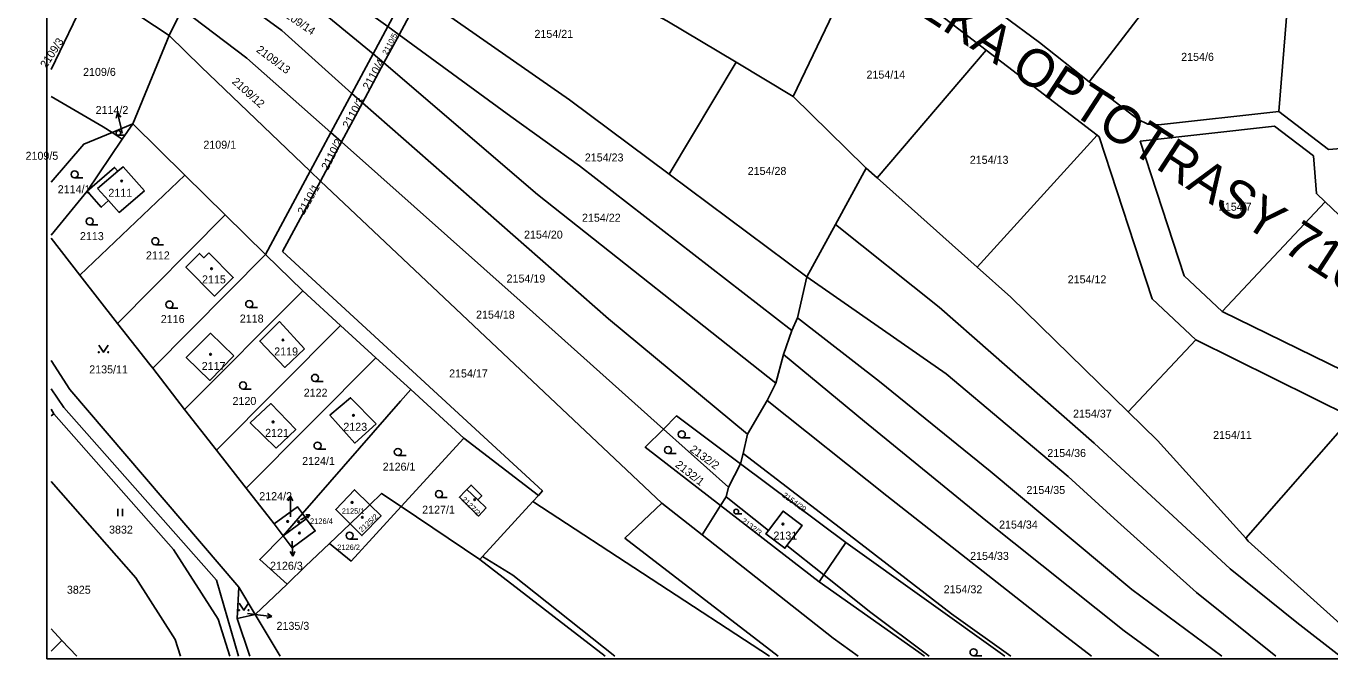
# Model space of a CAD drawing. Extents: x -606208 to -605570, y -1157873 to -1157573.
# Drawn here: x -606207.7 to -605930.7, y -1157873.5 to -1157739 of the extents above; entities that cross this region are included whole.
import ezdxf

# ---------------------------------------------------------------- set-up
doc = ezdxf.new("R2010")
doc.units = 0
for name, color, linetype in [('Vrstva 1', 7, 'Continuous'), ('Vrstva 30', 7, 'Continuous'), ('Vrstva 62', 7, 'Continuous')]:
    doc.layers.add(name, color=color, linetype=linetype)

msp = doc.modelspace()

# ---------------------------------------------------------------- linework, layer by layer
at = {"layer": 'Vrstva 1'}
msp.add_lwpolyline([(-606203.28, -1157873.46), (-605573.29, -1157873.46), (-605573.29, -1157576.47), (-606203.28, -1157576.47)], close=True, dxfattribs=at)
at = {"layer": 'Vrstva 62'}
for p, q in [((-606130.89, -1157739.11), (-606159.85, -1157718.17)), ((-605981.87, -1157750.81), (-605961.6, -1157724.39)), ((-606202.41, -1157748.21), (-606193.72, -1157730.15)), ((-606177.29, -1157741.01), (-606193.72, -1157730.15)), ((-606130.89, -1157739.11), (-606126.5, -1157730.93)), ((-606128.47, -1157740.84), (-606123.99, -1157732.49)), ((-606003.76, -1157744.1), (-606016.54, -1157734.29)), ((-605939.73, -1157734.56), (-605941.6, -1157757.14)), ((-606177.29, -1157741.01), (-606174.52, -1157735.38)), ((-606133.98, -1157744.86), (-606130.89, -1157739.11)), ((-606128.47, -1157740.84), (-606130.89, -1157739.11)), ((-606177.29, -1157741.01), (-606185.06, -1157759.77)), ((-606131.67, -1157746.79), (-606128.47, -1157740.84)), ((-606138.5, -1157753.29), (-606133.98, -1157744.86)), ((-606131.67, -1157746.79), (-606133.98, -1157744.86)), ((-606003.76, -1157744.1), (-606026.9, -1157771.24)), ((-605980.17, -1157762.2), (-606003.76, -1157744.1)), ((-606136.24, -1157755.3), (-606131.67, -1157746.79)), ((-606071.11, -1157770.44), (-606056.89, -1157746.69)), ((-606056.89, -1157746.69), (-606044.76, -1157753.96)), ((-606142.97, -1157761.61), (-606138.5, -1157753.29)), ((-606136.24, -1157755.3), (-606138.5, -1157753.29)), ((-606140.69, -1157763.6), (-606136.24, -1157755.3)), ((-606189.45, -1157761.59), (-606185.06, -1157759.77)), ((-606188.29, -1157757.46), (-606188.55, -1157758.54)), ((-606187.61, -1157760.38), (-606188.29, -1157757.46)), ((-606188.29, -1157757.46), (-606187.57, -1157758.32)), ((-606185.06, -1157759.77), (-606187.26, -1157763.02)), ((-606173.97, -1157770.68), (-606185.06, -1157759.77)), ((-606187.26, -1157763.02), (-606189.45, -1157761.59)), ((-606188.08, -1157762.2), (-606186.9, -1157762.2)), ((-606187.3, -1157761.72), (-606187.61, -1157760.38)), ((-606147.38, -1157769.84), (-606142.97, -1157761.61)), ((-606140.69, -1157763.6), (-606142.97, -1157761.61)), ((-605980.17, -1157762.2), (-606005.69, -1157790.23)), ((-606145.18, -1157771.95), (-606140.69, -1157763.6)), ((-606173.97, -1157770.68), (-606196.3, -1157791.9)), ((-606192.5, -1157773.52), (-606188.21, -1157769.85)), ((-606165.41, -1157779.09), (-606173.97, -1157770.68)), ((-606156.86, -1157787.5), (-606147.38, -1157769.84)), ((-606145.18, -1157771.95), (-606147.38, -1157769.84)), ((-606041.87, -1157792.26), (-606071.11, -1157770.44)), ((-606035.78, -1157781.12), (-606029.24, -1157769.15)), ((-606029.24, -1157769.15), (-606026.9, -1157771.24)), ((-606197.4, -1157771.25), (-606195.65, -1157771.25)), ((-606192.5, -1157773.52), (-606190.23, -1157776.04)), ((-606153.2, -1157786.89), (-606145.18, -1157771.95)), ((-606072.68, -1157840.36), (-606145.18, -1157771.95)), ((-606026.9, -1157771.24), (-606005.69, -1157790.23)), ((-605953.58, -1157799.65), (-605931.72, -1157776.35)), ((-606188.29, -1157802.2), (-606165.41, -1157779.09)), ((-606156.86, -1157787.5), (-606165.41, -1157779.09)), ((-606194.2, -1157781.23), (-606192.45, -1157781.23)), ((-606041.87, -1157792.26), (-606035.78, -1157781.12)), ((-606202.41, -1157784.06), (-606196.3, -1157791.9)), ((-606180.8, -1157811.7), (-606156.86, -1157787.5)), ((-606180.24, -1157785.45), (-606178.49, -1157785.45)), ((-606148.94, -1157795.28), (-606156.86, -1157787.5)), ((-606196.3, -1157791.9), (-606188.29, -1157802.2)), ((-606043.85, -1157800.98), (-606041.87, -1157792.26)), ((-606174.05, -1157820.44), (-606148.94, -1157795.28)), ((-606140.91, -1157802.61), (-606148.94, -1157795.28)), ((-606177.25, -1157798.91), (-606175.5, -1157798.91)), ((-606160.3, -1157798.81), (-606158.55, -1157798.81)), ((-606045.05, -1157803.71), (-606043.85, -1157800.98)), ((-606167.27, -1157829.08), (-606140.91, -1157802.61)), ((-606133.39, -1157809.47), (-606140.91, -1157802.61)), ((-606046.81, -1157808.74), (-606045.05, -1157803.71)), ((-605959.22, -1157805.66), (-605973.57, -1157820.96)), ((-605926.07, -1157822.08), (-605959.22, -1157805.66)), ((-606160.96, -1157837.17), (-606133.39, -1157809.47)), ((-606126, -1157816.22), (-606133.39, -1157809.47)), ((-606048.4, -1157814.88), (-606046.81, -1157808.74)), ((-606180.8, -1157811.7), (-606174.05, -1157820.44)), ((-606146.34, -1157814.5), (-606144.59, -1157814.5)), ((-606050.27, -1157818.52), (-606048.4, -1157814.88)), ((-606202.41, -1157816.09), (-606199.69, -1157820.04)), ((-606161.63, -1157816.11), (-606159.88, -1157816.11)), ((-606114.7, -1157826.53), (-606126, -1157816.22)), ((-606201.78, -1157821.35), (-606202.41, -1157820.41)), ((-606199.69, -1157820.04), (-606167.24, -1157856.73)), ((-606174.05, -1157820.44), (-606167.27, -1157829.08)), ((-606054.42, -1157825.73), (-606050.27, -1157818.52)), ((-606201.78, -1157821.35), (-606202.41, -1157821.83)), ((-605926.07, -1157822.08), (-605948.61, -1157847.83)), ((-606058.49, -1157836.99), (-606072.32, -1157824.61)), ((-606055.38, -1157829.79), (-606054.42, -1157825.73)), ((-606145.79, -1157828.9), (-606144.04, -1157828.9)), ((-606128.03, -1157841.09), (-606114.7, -1157826.53)), ((-606098.87, -1157838.71), (-606114.7, -1157826.53)), ((-606068.41, -1157826.49), (-606066.66, -1157826.49)), ((-606167.27, -1157829.08), (-606160.96, -1157837.17)), ((-606128.73, -1157830.23), (-606126.98, -1157830.23)), ((-606071.33, -1157829.83), (-606069.58, -1157829.83)), ((-606055.91, -1157832.02), (-606055.38, -1157829.79)), ((-606058.49, -1157836.99), (-606055.91, -1157832.02)), ((-606160.96, -1157837.17), (-606154.97, -1157844.72)), ((-606058.97, -1157839.03), (-606058.49, -1157836.99)), ((-606151.56, -1157838.88), (-606152.06, -1157839.88)), ((-606151.56, -1157841.88), (-606151.56, -1157838.88)), ((-606151.56, -1157838.88), (-606151.06, -1157839.88)), ((-606120, -1157839.19), (-606118.25, -1157839.19)), ((-606114.05, -1157837.45), (-606111.74, -1157839.67)), ((-606110.73, -1157851.67), (-606100.03, -1157839.98)), ((-606100.03, -1157839.98), (-606098.87, -1157838.71)), ((-606049.75, -1157872.87), (-606100.03, -1157839.98)), ((-606060.18, -1157840.86), (-606058.97, -1157839.03)), ((-606050.01, -1157846.2), (-606058.97, -1157839.03)), ((-606188.19, -1157843.1), (-606188.19, -1157841.6)), ((-606187.19, -1157843.1), (-606187.19, -1157841.6)), ((-606153.08, -1157847.3), (-606148.97, -1157842.59)), ((-606151.56, -1157843.25), (-606151.56, -1157841.88)), ((-606149.4, -1157843.92), (-606147.41, -1157842.81)), ((-606148.97, -1157842.59), (-606148.17, -1157843.68)), ((-606147.41, -1157842.81), (-606148.26, -1157842.85)), ((-606147.41, -1157842.81), (-606147.89, -1157843.52)), ((-606138.89, -1157844.74), (-606134.7, -1157840.73)), ((-606128.03, -1157841.09), (-606111.34, -1157852.33)), ((-606072.68, -1157840.36), (-606064.09, -1157847.08)), ((-606064.09, -1157847.08), (-606060.18, -1157840.86)), ((-606056.83, -1157842.65), (-606055.66, -1157842.65)), ((-606154.97, -1157844.72), (-606153.08, -1157847.3)), ((-606148.17, -1157843.68), (-606153.08, -1157847.3)), ((-606143.27, -1157848.94), (-606138.89, -1157844.74)), ((-606151.17, -1157848.41), (-606151.16, -1157848.62)), ((-606138.98, -1157848.01), (-606137.23, -1157848.01)), ((-606151.06, -1157851.62), (-606151.59, -1157850.64)), ((-606151.16, -1157848.62), (-606151.06, -1157851.62)), ((-606151.06, -1157851.62), (-606150.59, -1157850.6)), ((-606038.21, -1157855.62), (-606033.59, -1157848.72)), ((-606111.34, -1157852.33), (-606110.73, -1157851.67)), ((-606167.24, -1157856.73), (-606162.59, -1157872.87)), ((-606039.19, -1157857.08), (-606038.21, -1157855.62)), ((-606162.53, -1157858.2), (-606162.86, -1157864.9)), ((-606159.01, -1157864.02), (-606162.53, -1157858.2)), ((-606152.26, -1157857.55), (-606159.01, -1157864.02)), ((-606159.01, -1157864.02), (-606162.86, -1157864.9)), ((-606160.67, -1157863.8), (-606158.48, -1157864.08)), ((-606158.48, -1157864.08), (-606155.5, -1157864.45)), ((-606155.5, -1157864.45), (-606156.56, -1157864.82)), ((-606155.5, -1157864.45), (-606156.43, -1157863.83)), ((-606200.08, -1157869.51), (-606202.41, -1157867.04)), ((-606202.41, -1157871.81), (-606200.08, -1157869.51)), ((-606196.91, -1157872.87), (-606200.08, -1157869.51)), ((-606006.42, -1157872.8), (-606004.67, -1157872.8))]:
    msp.add_line(p, q, dxfattribs=at)
for points in [[(-605985.7, -1157707.69), (-606001.7, -1157728.24), (-606000.3, -1157736.67), (-605992.45, -1157742.47), (-605981.87, -1157750.81)], [(-606056.89, -1157746.69), (-606071.62, -1157737.87), (-606088.96, -1157728.54), (-606113.74, -1157715.77)], [(-606133.98, -1157744.86), (-606143.4, -1157737.14), (-606163.89, -1157722.28)], [(-606138.5, -1157753.29), (-606153.37, -1157739.93), (-606169.28, -1157728.25)], [(-606031.93, -1157728.32), (-606035.41, -1157734.5), (-606044.76, -1157753.96)], [(-606123.99, -1157732.49), (-606092.27, -1157754.64), (-606071.11, -1157770.44)], [(-606142.97, -1157761.61), (-606160.8, -1157745.8), (-606174.52, -1157735.38)], [(-606147.38, -1157769.84), (-606170.48, -1157747.64), (-606177.29, -1157741.01)], [(-606045.05, -1157803.71), (-606090.11, -1157768.67), (-606104.75, -1157758.18), (-606128.47, -1157740.84)], [(-606048.4, -1157814.88), (-606099.09, -1157774.75), (-606131.67, -1157746.79)], [(-605981.87, -1157750.81), (-605971.44, -1157758.81), (-605969.4, -1157759.83), (-605967.12, -1157760.01), (-605941.6, -1157757.14)], [(-606189.45, -1157761.59), (-606191.32, -1157760.37), (-606202.41, -1157753.93)], [(-606044.76, -1157753.96), (-606029.55, -1157768.87), (-606029.24, -1157769.15)], [(-606054.42, -1157825.73), (-606083.97, -1157801.22), (-606136.24, -1157755.3)], [(-605941.6, -1157757.14), (-605931.04, -1157765.25), (-605923.02, -1157764.61), (-605918.26, -1157759.56)], [(-606202.41, -1157772.15), (-606195.45, -1157764.08), (-606189.45, -1157761.59)], [(-605959.22, -1157805.66), (-605968.49, -1157796.97), (-605979.72, -1157762.54), (-605980.17, -1157762.2)], [(-605931.72, -1157776.35), (-605933.58, -1157774.6), (-605934.23, -1157766.58), (-605942.47, -1157760.26), (-605971, -1157763.47), (-605961.68, -1157792.05), (-605953.58, -1157799.65)], [(-606187.26, -1157763.02), (-606194.76, -1157774.09), (-606202.41, -1157783.43)], [(-606072.32, -1157824.61), (-606102.77, -1157797.36), (-606140.69, -1157763.6)], [(-606182.56, -1157774), (-606187.09, -1157768.89), (-606188.21, -1157769.85), (-606188.91, -1157769.03), (-606194.76, -1157774.09), (-606191.72, -1157777.5), (-606190.23, -1157776.04), (-606187.95, -1157778.58), (-606182.56, -1157774)], [(-605953.58, -1157799.65), (-605927.83, -1157812.28), (-605920.8, -1157811.02), (-605907.64, -1157797.07), (-605907.89, -1157788.58), (-605918.83, -1157778.27), (-605928.82, -1157779.07), (-605931.72, -1157776.35)], [(-605928.51, -1157872.87), (-605937.76, -1157865.73), (-605951.92, -1157854.34), (-605980.77, -1157827.6), (-606013.72, -1157798.74), (-606035.78, -1157781.12)], [(-606168.87, -1157787.17), (-606169.93, -1157788.21), (-606170.83, -1157787.29), (-606173.76, -1157790.23), (-606167.66, -1157796.36), (-606163.68, -1157792.38), (-606168.87, -1157787.17)], [(-606098.87, -1157838.71), (-606098, -1157837.77), (-606153.2, -1157786.89)], [(-606005.69, -1157790.23), (-605998.54, -1157796.62), (-605973.57, -1157820.96)], [(-605942.2, -1157872.87), (-605959.06, -1157859.37), (-605976.53, -1157843.61), (-605986.33, -1157834.67), (-606012.26, -1157812.91), (-606041.87, -1157792.26)], [(-605953.7, -1157872.87), (-605972.83, -1157858.7), (-606002.87, -1157833.55), (-606026.42, -1157814.49), (-606043.85, -1157800.98)], [(-606188.29, -1157802.2), (-606181.44, -1157810.87), (-606180.8, -1157811.7)], [(-606148.57, -1157807.57), (-606153.85, -1157801.79), (-606158.05, -1157805.91), (-606152.76, -1157811.52), (-606148.57, -1157807.57)], [(-606192.26, -1157806.8), (-606191.26, -1157808.3), (-606190.26, -1157806.8)], [(-606163.59, -1157809.05), (-606168.55, -1157804.25), (-606173.68, -1157809.43), (-606168.67, -1157814.29), (-606163.59, -1157809.05)], [(-605967.09, -1157872.87), (-605974.42, -1157867.5), (-606003.8, -1157844.07), (-606029.6, -1157823.02), (-606046.81, -1157808.74)], [(-606162.53, -1157858.2), (-606198.4, -1157816.23), (-606202.41, -1157810.02)], [(-606148.97, -1157842.59), (-606128.13, -1157818.69), (-606126, -1157816.22)], [(-606133.34, -1157823.51), (-606138.77, -1157817.95), (-606143.17, -1157821.7), (-606137.87, -1157827.59), (-606133.34, -1157823.51)], [(-606154.6, -1157828.71), (-606150.41, -1157824.7), (-606155.68, -1157819.19), (-606160.1, -1157823.26), (-606154.6, -1157828.71)], [(-605981.38, -1157872.87), (-605987.54, -1157868.15), (-606024.87, -1157838.8), (-606050.27, -1157818.52)], [(-606164.4, -1157872.87), (-606166.91, -1157865.04), (-606176.41, -1157850.18), (-606201.78, -1157821.35)], [(-606055.91, -1157832.02), (-606069.56, -1157821.81), (-606072.32, -1157824.61)], [(-605973.57, -1157820.96), (-605967.32, -1157827.06), (-605948.61, -1157847.83)], [(-606072.32, -1157824.61), (-606076.16, -1157828.5), (-606060.18, -1157840.86)], [(-605998.51, -1157872.87), (-606011.08, -1157863.9), (-606032.85, -1157847.1), (-606055.38, -1157829.79)], [(-605999.78, -1157872.87), (-606033.59, -1157848.72), (-606055.91, -1157832.02)], [(-606174.9, -1157872.87), (-606176.04, -1157869.33), (-606184.42, -1157856.21), (-606202.41, -1157835.77)], [(-606109.97, -1157841.38), (-606111.62, -1157843.1), (-606115.66, -1157839.12), (-606114.41, -1157837.81), (-606114.05, -1157837.45), (-606113.17, -1157836.53), (-606110.91, -1157838.8), (-606111.74, -1157839.67), (-606109.97, -1157841.38)], [(-606134.7, -1157840.73), (-606137.97, -1157837.53), (-606141.92, -1157841.74), (-606138.89, -1157844.74)], [(-606134.7, -1157840.73), (-606132.17, -1157838.3), (-606128.03, -1157841.09)], [(-606154.97, -1157844.72), (-606150.05, -1157841.12), (-606148.97, -1157842.59)], [(-606143.27, -1157848.94), (-606138.64, -1157852.67), (-606128.03, -1157841.09)], [(-606138.89, -1157844.74), (-606136.36, -1157847.25), (-606132.28, -1157843.09), (-606134.7, -1157840.73)], [(-606047.91, -1157872.87), (-606080.48, -1157847.77), (-606072.68, -1157840.36)], [(-606060.18, -1157840.86), (-606039.19, -1157857.08), (-606016.82, -1157872.87)], [(-606046.06, -1157849.35), (-606042.83, -1157845.13), (-606046.88, -1157842.06), (-606050.01, -1157846.2)], [(-606148.17, -1157843.68), (-606146.28, -1157846.26), (-606151.2, -1157849.87), (-606153.08, -1157847.3)], [(-606153.08, -1157847.3), (-606158.06, -1157852.34), (-606152.26, -1157857.55)], [(-606030.95, -1157872.87), (-606036.22, -1157869.02), (-606064.09, -1157847.08)], [(-606050.01, -1157846.2), (-606050.53, -1157846.89), (-606046.51, -1157849.93), (-606046.06, -1157849.35)], [(-605948.61, -1157847.83), (-605948.07, -1157848.43), (-605920.91, -1157872.87)], [(-606152.26, -1157857.55), (-606148.33, -1157853.78), (-606143.27, -1157848.94)], [(-606015.84, -1157872.87), (-606028.52, -1157863.36), (-606038.21, -1157855.62), (-606046.06, -1157849.35)], [(-606084.67, -1157872.87), (-606111.34, -1157852.33)], [(-606082.66, -1157872.87), (-606104.3, -1157855.69), (-606110.73, -1157851.67)], [(-606162.44, -1157861.6), (-606161.44, -1157863.1), (-606160.44, -1157861.6)], [(-606162.86, -1157864.9), (-606160.16, -1157872.87)], [(-606153.74, -1157872.87), (-606159.01, -1157864.02)]]:
    msp.add_lwpolyline(points, dxfattribs=at)
for centre, radius in [((-606188.08, -1157761.7), 0.502), ((-606197.4, -1157770.5), 0.75), ((-606187.41, -1157771.92), 0.175), ((-606194.2, -1157780.48), 0.75), ((-606180.24, -1157784.7), 0.75), ((-606168.3, -1157790.55), 0.175), ((-606177.25, -1157798.16), 0.75), ((-606160.3, -1157798.06), 0.75), ((-606153.12, -1157805.69), 0.175), ((-606192.26, -1157808.3), 0.1), ((-606190.26, -1157808.3), 0.1), ((-606168.52, -1157808.73), 0.175), ((-606161.63, -1157815.36), 0.75), ((-606146.34, -1157813.75), 0.75), ((-606155.22, -1157823.09), 0.175), ((-606138.16, -1157821.7), 0.175), ((-606068.41, -1157825.74), 0.75), ((-606145.79, -1157828.15), 0.75), ((-606128.73, -1157829.48), 0.75), ((-606071.33, -1157829.08), 0.75), ((-606138.44, -1157840.21), 0.175), ((-606120, -1157838.44), 0.75), ((-606112.4, -1157839.63), 0.175), ((-606056.84, -1157842.15), 0.502), ((-606152.12, -1157844.25), 0.175), ((-606149.81, -1157844.32), 0.175), ((-606136.28, -1157843.36), 0.175), ((-606046.94, -1157844.82), 0.175), ((-606149.63, -1157846.69), 0.175), ((-606138.98, -1157847.26), 0.75), ((-606162.44, -1157863.1), 0.1), ((-606160.44, -1157863.1), 0.1), ((-606006.42, -1157872.05), 0.75)]:
    msp.add_circle(centre, radius, dxfattribs=at)

# ---------------------------------------------------------------- texts
at = {"layer": 'Vrstva 30'}
msp.add_text('DÉLKA OPTOTRASY 710m', height=8, rotation=326.99, dxfattribs=at).set_placement((-606030.83, -1157728.28))
at = {"layer": 'Vrstva 62'}
for s, height, rotation, p in [('2109/14', 1.7, 326, (-606153.81, -1157736.39)), ('2109/3', 1.7, 57, (-606203.41, -1157748.05)), ('2109/13', 1.7, 323, (-606158.94, -1157744.32)), ('2110/5', 1.19, 62, (-606131.06, -1157745.19)), ('2110/4', 1.7, 61, (-606134.84, -1157752.68)), ('2109/12', 1.7, 318, (-606164.09, -1157750.99)), ('2110/3', 1.7, 61, (-606139.13, -1157760.89)), ('2110/2', 1.7, 63, (-606143.58, -1157769.7)), ('2110/1', 1.7, 60, (-606148.72, -1157779.23)), ('2132/2', 1.7, 324, (-606066.85, -1157829.24)), ('2132/1', 1.7, 322, (-606069.93, -1157832.5)), ('2127/2', 1.14, 315, (-606115.29, -1157839.69)), ('2154/29', 1.19, 324, (-606047.15, -1157838.94)), ('2125/2', 1.14, 42, (-606136.39, -1157846.61)), ('2132/3', 1.19, 323, (-606055.87, -1157844.37))]:
    msp.add_text(s, height=height, rotation=rotation, dxfattribs=at).set_placement(p)
for s, height, p in [('2154/21', 1.7, (-606099.71, -1157741.5)), ('2154/6', 1.7, (-605962.32, -1157746.38)), ('2109/6', 1.7, (-606195.6, -1157749.58)), ('2154/14', 1.7, (-606029.17, -1157750.15)), ('2114/2', 1.7, (-606192.94, -1157757.67)), ('2109/1', 1.7, (-606170.04, -1157765.05)), ('2109/5', 1.7, (-606207.82, -1157767.4)), ('2154/23', 1.7, (-606089.01, -1157767.76)), ('2154/13', 1.7, (-606007.23, -1157768.26)), ('2154/28', 1.7, (-606054.41, -1157770.62)), ('2114/1', 1.7, (-606200.98, -1157774.51)), ('2111', 1.7, (-606190.23, -1157775.27)), ('2154/7', 1.7, (-605954.31, -1157778.23)), ('2154/22', 1.7, (-606089.61, -1157780.56)), ('2113', 1.7, (-606196.26, -1157784.47)), ('2154/20', 1.7, (-606101.92, -1157784.15)), ('2112', 1.7, (-606182.24, -1157788.57)), ('2115', 1.7, (-606170.33, -1157793.67)), ('2154/19', 1.7, (-606105.63, -1157793.48)), ('2154/12', 1.7, (-605986.43, -1157793.66)), ('2116', 1.7, (-606179.09, -1157802.09)), ('2118', 1.7, (-606162.3, -1157801.99)), ('2154/18', 1.7, (-606112.11, -1157801.15)), ('2119', 1.7, (-606154.99, -1157808.98)), ('2135/11', 1.7, (-606194.29, -1157812.79)), ('2117', 1.7, (-606170.39, -1157812.07)), ('2154/17', 1.7, (-606117.84, -1157813.65)), ('2120', 1.7, (-606163.85, -1157819.5)), ('2122', 1.7, (-606148.73, -1157817.74)), ('2154/37', 1.7, (-605985.29, -1157822.19)), ('2123', 1.7, (-606140.31, -1157824.99)), ('2121', 1.7, (-606156.93, -1157826.27)), ('2154/11', 1.7, (-605955.54, -1157826.72)), ('2154/36', 1.7, (-605990.76, -1157830.56)), ('2124/1', 1.7, (-606149.06, -1157832.25)), ('2126/1', 1.7, (-606131.95, -1157833.46)), ('2154/35', 1.7, (-605995.19, -1157838.41)), ('2124/2', 1.7, (-606158.17, -1157839.73)), ('2125/1', 1.14, (-606140.64, -1157842.6)), ('2127/1', 1.7, (-606123.57, -1157842.6)), ('3832', 1.7, (-606190.08, -1157846.83)), ('2126/4', 1.19, (-606147.4, -1157844.79)), ('2154/34', 1.7, (-606001, -1157845.76)), ('2131', 1.7, (-606048.94, -1157848.1)), ('2126/2', 1.14, (-606141.59, -1157850.3)), ('2154/33', 1.7, (-606007.15, -1157852.42)), ('2126/3', 1.7, (-606155.88, -1157854.51)), ('3825', 1.7, (-606199.03, -1157859.61)), ('2154/32', 1.7, (-606012.78, -1157859.51)), ('2135/3', 1.7, (-606154.5, -1157867.28))]:
    msp.add_text(s, height=height, dxfattribs=at).set_placement(p)

doc.saveas('drawing.dxf')
